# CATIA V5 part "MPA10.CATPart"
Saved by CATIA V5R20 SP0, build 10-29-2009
Part number: MPA10
Definition: NONE
Nomenclature: MPA10
Source: Unknown
Description: MPA10
Bounding box of the stored display mesh (mm): x 0 to 12, y -5 to 5, z -5 to 5
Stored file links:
  C:\Users\Utente\Desktop\IO LAVORO\3D X SITO CF\X SITO\PLASTICA\CFMR\MPA10.CATPart
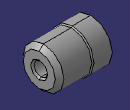
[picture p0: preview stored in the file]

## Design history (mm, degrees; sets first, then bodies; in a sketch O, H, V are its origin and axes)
Body1 "MPA10" (main body)
  Solid1: solid without history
